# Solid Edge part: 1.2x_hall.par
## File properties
Author: Romil
Template: iso part.par
Last saved by: Romil
Revision: 41
Application: Solid Edge
Accuracy: 0.990
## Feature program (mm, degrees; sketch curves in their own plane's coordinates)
sketch used by "unnamed Protrusion 1" plane through (0, 0, 0) normal (1, 0, 0) x-axis (0, 1, 0)
  arc centre (-1.8031, 1.8031) radius 0.9025 from (-0.9006, 1.8031) to (-1.8031, 0.9006) cw
  line (-0.9006, 2.3857) -> (-0.9006, 1.8031)
  arc centre (0, 0) radius 2.55 from (-0.9006, 2.3857) to (1.6939, 1.9061) cw
  line (-1.8031, 0.9006) -> (-2.3857, 0.9006)
  arc centre (1.8031, -1.8031) radius 0.9025 from (0.9006, -1.8031) to (1.8031, -0.9006) cw
  line (0.9006, -2.3857) -> (0.9006, -1.8031)
  arc centre (0, 0) radius 2.55 from (0.9006, -2.3857) to (-1.6939, -1.9061) cw
  line (1.8031, -0.9006) -> (2.3857, -0.9006)
  line (-1.0607, -1.2728) -> (-1.6939, -1.9061)
  arc centre (-1.1667, -1.1667) radius 0.15 from (-1.2728, -1.0607) to (-1.0607, -1.2728) cw
  line (-1.9061, -1.6939) -> (-1.2728, -1.0607)
  line (1.9061, 1.6939) -> (1.2728, 1.0607)
  arc centre (1.1667, 1.1667) radius 0.15 from (1.2728, 1.0607) to (1.0607, 1.2728) cw
  line (1.0607, 1.2728) -> (1.6939, 1.9061)
  arc centre (0, 0) radius 2.55 from (1.9061, 1.6939) to (2.3857, -0.9006) cw
  arc centre (0, 0) radius 2.55 from (-2.5456, 0.15) to (-2.3857, 0.9006) cw
  arc centre (0, 0) radius 2.55 from (-1.9061, -1.6939) to (-2.3857, 0.9006) cw
  circle centre (0, 0) radius 3.6
extrude "unnamed Protrusion 1" add finite 3.8 symmetric
sketch for "ExtrudedCutout_36" plane through (0, 0, 0) normal (1, 0, 0) x-axis (0, 1, 0)
  arc centre (0, 0) radius 2.55 from (-0.9006, 2.3857) to (1.6939, 1.9061) cw
  line (1.0607, 1.2728) -> (1.6939, 1.9061)
  arc centre (1.1667, 1.1667) radius 0.15 from (1.2728, 1.0607) to (1.0607, 1.2728) cw
  line (1.9061, 1.6939) -> (1.2728, 1.0607)
  arc centre (0, 0) radius 2.55 from (1.9061, 1.6939) to (2.3857, -0.9006) cw
  line (1.8031, -0.9006) -> (2.3857, -0.9006)
  arc centre (1.8031, -1.8031) radius 0.9025 from (0.9006, -1.8031) to (1.8031, -0.9006) cw
  line (0.9006, -2.3857) -> (0.9006, -1.8031)
  arc centre (0, 0) radius 2.55 from (0.9006, -2.3857) to (-1.6939, -1.9061) cw
  line (-1.0607, -1.2728) -> (-1.6939, -1.9061)
  arc centre (-1.1667, -1.1667) radius 0.15 from (-1.2728, -1.0607) to (-1.0607, -1.2728) cw
  line (-1.9061, -1.6939) -> (-1.2728, -1.0607)
  arc centre (0, 0) radius 2.55 from (-1.9061, -1.6939) to (-2.3857, 0.9006) cw
  line (-1.8031, 0.9006) -> (-2.3857, 0.9006)
  arc centre (-1.8031, 1.8031) radius 0.9025 from (-0.9006, 1.8031) to (-1.8031, 0.9006) cw
  line (-0.9006, 2.3857) -> (-0.9006, 1.8031)
extrude "ExtrudedCutout_36" cut finite 46.2247 symmetric
sketch for "unnamed RevolvedCutout 1" plane through (0, 0, 0) normal (0, -1, 0) x-axis (1, 0, 0)
  line (-1.9, 4.6479) -> (1.9, 4.6479)
  line (1.9, 4.6479) -> (1.9, 3.6)
  line (1.9, 3.6) -> (0.835, 3.6)
  arc centre (0.835, 3.4) radius 0.2 from (0.635, 3.4) to (0.835, 3.6) cw
  line (0.635, 3.05) -> (0.635, 3.4)
  arc centre (0.335, 3.05) radius 0.3 from (0.335, 2.75) to (0.635, 3.05) ccw
  line (0.335, 2.75) -> (-0.335, 2.75)
  arc centre (-0.335, 3.05) radius 0.3 from (-0.335, 2.75) to (-0.635, 3.05) cw
  line (-0.635, 3.05) -> (-0.635, 3.4)
  arc centre (-0.835, 3.4) radius 0.2 from (-0.835, 3.6) to (-0.635, 3.4) cw
  line (-0.835, 3.6) -> (-1.9, 3.6)
  line (-1.9, 3.6) -> (-1.9, 4.6479)
revolve "unnamed RevolvedCutout 1" cut finite 360 deg
fillet "Round_11" radius 0.2
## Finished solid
Body 1: solid body, 29 faces, 60 edges, 32 vertices.
  Faces by surface: plane 12, cylinder 11, torus 6
  Edges by curve: line 32, circle 28
Bounding box of the edges (mm; curved faces can reach further): 3.800 x 7.200 x 7.200, from (-1.9, -3.6, -3.6) to (1.9, 3.6, 3.6).
Cylindrical faces by radius (mm): R0.15 x2, R0.9025 x2, R2.55 x4, R2.75 x1, R3.6 x2
Toroidal faces (ring radius, tube radius in mm): R3.05 r0.3 x2, R3.4 r0.2 x4
Planar faces by outward normal: +x 2, +y 1, +z 1, -x 2, -y 1, -z 1, oblique 4
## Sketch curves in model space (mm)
line (-2.4774, 0, 0) -> (5.0483, 0, 0)
arc centre (-0.335, 0, 3.05) radius 0.3 from (-0.335, 0, 2.75) through (-0.5532, 0, 2.8441) to (-0.635, 0, 3.05)
line (-0.635, 0, 3.05) -> (-0.635, 0, 3.4)
arc centre (-0.835, 0, 3.4) radius 0.2 from (-0.835, 0, 3.6) through (-0.6895, 0, 3.5372) to (-0.635, 0, 3.4)
line (-0.835, 0, 3.6) -> (-1.9, 0, 3.6)
line (-1.9, 0, 3.6) -> (-1.9, 0, 4.6479)
line (-1.9, 0, 4.6479) -> (1.9, 0, 4.6479)
line (1.9, 0, 4.6479) -> (1.9, 0, 3.6)
line (1.9, 0, 3.6) -> (0.835, 0, 3.6)
arc centre (0.835, 0, 3.4) radius 0.2 from (0.635, 0, 3.4) through (0.6978, 0, 3.5455) to (0.835, 0, 3.6)
line (0.635, 0, 3.05) -> (0.635, 0, 3.4)
arc centre (0.335, 0, 3.05) radius 0.3 from (0.335, 0, 2.75) through (0.5532, 0, 2.8441) to (0.635, 0, 3.05)
line (0.335, 0, 2.75) -> (-0.335, 0, 2.75)
circle centre (0, 0, 0) radius 3.6
arc centre (0, 0, 0) radius 2.55 from (0, -2.5456, 0.15) through (0, -2.494, 0.5314) to (0, -2.3857, 0.9006)
line (0, -1.8031, 0.9006) -> (0, -2.3857, 0.9006)
arc centre (0, 0, 0) radius 2.55 from (0, -1.9061, -1.6939) through (0, -2.5075, -0.4635) to (0, -2.3857, 0.9006)
line (0, -1.9061, -1.6939) -> (0, -1.2728, -1.0607)
arc centre (0, -1.1667, -1.1667) radius 0.15 from (0, -1.2728, -1.0607) through (0, -1.0576, -1.0638) to (0, -1.0607, -1.2728)
line (0, -1.0607, -1.2728) -> (0, -1.6939, -1.9061)
arc centre (0, 0, 0) radius 2.55 from (0, 0.9006, -2.3857) through (0, -0.4635, -2.5075) to (0, -1.6939, -1.9061)
line (0, 0.9006, -2.3857) -> (0, 0.9006, -1.8031)
arc centre (0, 1.8031, -1.8031) radius 0.9025 from (0, 0.9006, -1.8031) through (0, 1.1838, -1.1467) to (0, 1.8031, -0.9006)
line (0, 1.8031, -0.9006) -> (0, 2.3857, -0.9006)
arc centre (0, 0, 0) radius 2.55 from (0, 1.9061, 1.6939) through (0, 2.5075, 0.4635) to (0, 2.3857, -0.9006)
line (0, 1.9061, 1.6939) -> (0, 1.2728, 1.0607)
arc centre (0, 1.1667, 1.1667) radius 0.15 from (0, 1.2728, 1.0607) through (0, 1.0576, 1.0638) to (0, 1.0607, 1.2728)
line (0, 1.0607, 1.2728) -> (0, 1.6939, 1.9061)
arc centre (0, 0, 0) radius 2.55 from (0, -0.9006, 2.3857) through (0, 0.4635, 2.5075) to (0, 1.6939, 1.9061)
line (0, -0.9006, 2.3857) -> (0, -0.9006, 1.8031)
arc centre (0, -1.8031, 1.8031) radius 0.9025 from (0, -0.9006, 1.8031) through (0, -1.1838, 1.1467) to (0, -1.8031, 0.9006)
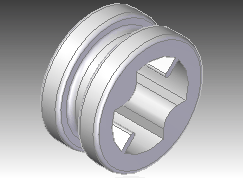
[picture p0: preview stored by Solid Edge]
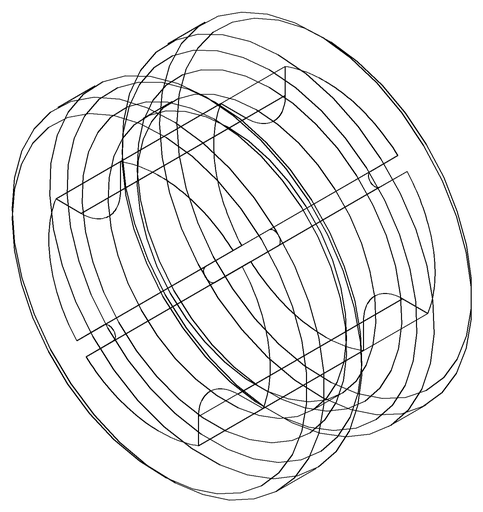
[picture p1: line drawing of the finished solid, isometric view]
